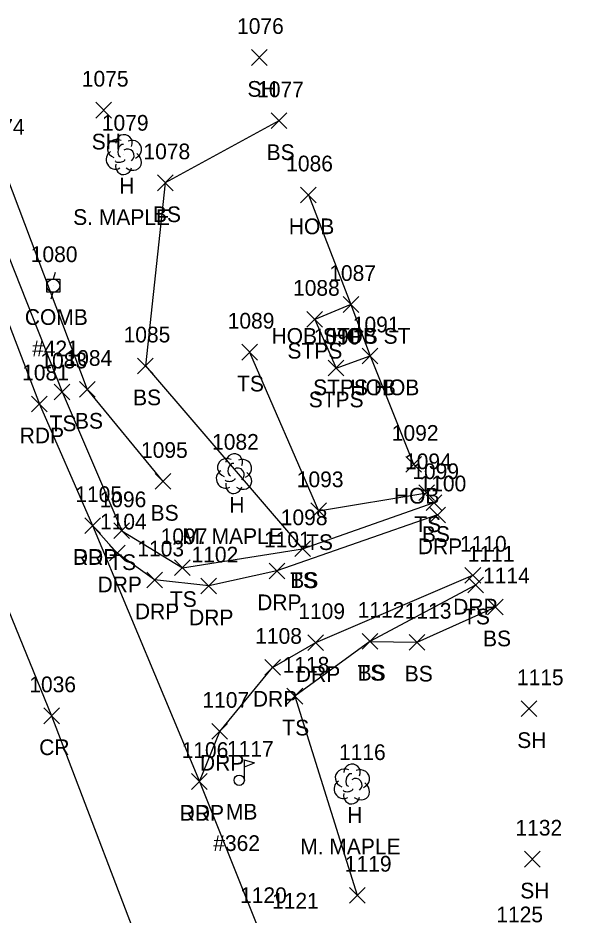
# Model space of a CAD drawing. Extents: x 1651305 to 1654558, y 539481 to 548441.
# Drawn here: x 1654147.7 to 1654218.4, y 545082.1 to 545196.3 of the extents above; entities that cross this region are included whole.
import ezdxf

# ---------------------------------------------------------------- set-up
doc = ezdxf.new("R2010")
doc.units = 0
for name, color, linetype in [('L_A', 7, 'Continuous'), ('L_C', 7, 'Continuous'), ('L_I', 7, 'Continuous'), ('L_TIC', 7, 'Continuous'), ('LBC', 7, 'Continuous'), ('LBF', 7, 'Continuous'), ('LELB', 7, 'Continuous'), ('LMB', 7, 'Continuous'), ('LTD', 7, 'Continuous'), ('P_A', 7, 'Continuous'), ('P_I', 7, 'Continuous'), ('P_TIC', 7, 'Continuous'), ('PET', 7, 'Continuous'), ('PRC', 7, 'Continuous'), ('R_A', 7, 'Continuous'), ('R_I', 7, 'Continuous'), ('R_TIC', 7, 'Continuous'), ('RDP', 7, 'Continuous'), ('U_A', 7, 'Continuous'), ('U_C', 7, 'Continuous'), ('U_I', 7, 'Continuous'), ('UP', 7, 'Continuous')]:
    doc.layers.add(name, color=color, linetype=linetype)

msp = doc.modelspace()

# ---------------------------------------------------------------- linework, layer by layer
at = {"layer": 'L_TIC'}
for points in [[(1654177.39, 545190.31), (1654179.39, 545192.31)], [(1654179.39, 545190.31), (1654177.39, 545192.31)], [(1654157.57, 545183.6), (1654159.57, 545185.6)], [(1654159.57, 545183.6), (1654157.57, 545185.6)], [(1654179.89, 545182.25), (1654181.89, 545184.25)], [(1654181.89, 545182.25), (1654179.89, 545184.25)], [(1654165.41, 545174.35), (1654167.41, 545176.35)], [(1654167.41, 545174.35), (1654165.41, 545176.35)], [(1654183.65, 545172.81), (1654185.65, 545174.81)], [(1654185.65, 545172.81), (1654183.65, 545174.81)], [(1654189.07, 545158.86), (1654191.07, 545160.86)], [(1654191.07, 545158.86), (1654189.07, 545160.86)], [(1654189.07, 545158.86), (1654191.07, 545160.86)], [(1654191.07, 545158.86), (1654189.07, 545160.86)], [(1654184.46, 545156.97), (1654186.46, 545158.97)], [(1654186.46, 545156.97), (1654184.46, 545158.97)], [(1654176.15, 545152.79), (1654178.15, 545154.79)], [(1654178.15, 545152.79), (1654176.15, 545154.79)], [(1654191.5, 545152.31), (1654193.5, 545154.31)], [(1654193.5, 545152.31), (1654191.5, 545154.31)], [(1654191.5, 545152.31), (1654193.5, 545154.31)], [(1654193.5, 545152.31), (1654191.5, 545154.31)], [(1654162.88, 545151.03), (1654164.88, 545153.03)], [(1654164.88, 545151.03), (1654162.88, 545153.03)], [(1654187.17, 545150.77), (1654189.17, 545152.77)], [(1654189.17, 545150.77), (1654187.17, 545152.77)], [(1654155.48, 545148.05), (1654157.48, 545150.05)], [(1654157.48, 545148.05), (1654155.48, 545150.05)], [(1654152.28, 545147.73), (1654154.28, 545149.73)], [(1654154.28, 545147.73), (1654152.28, 545149.73)], [(1654197.04, 545138.51), (1654199.04, 545140.51)], [(1654199.04, 545138.51), (1654197.04, 545140.51)], [(1654165.11, 545136.33), (1654167.11, 545138.33)], [(1654167.11, 545136.33), (1654165.11, 545138.33)], [(1654198.72, 545134.89), (1654200.72, 545136.89)], [(1654200.72, 545134.89), (1654198.72, 545136.89)], [(1654199.66, 545133.63), (1654201.66, 545135.63)], [(1654201.66, 545133.63), (1654199.66, 545135.63)], [(1654184.94, 545132.6), (1654186.94, 545134.6)], [(1654186.94, 545132.6), (1654184.94, 545134.6)], [(1654159.88, 545130.05), (1654161.88, 545132.05)], [(1654161.88, 545130.05), (1654159.88, 545132.05)], [(1654182.9, 545127.76), (1654184.9, 545129.76)], [(1654184.9, 545127.76), (1654182.9, 545129.76)], [(1654182.9, 545127.76), (1654184.9, 545129.76)], [(1654184.9, 545127.76), (1654182.9, 545129.76)], [(1654167.6, 545125.35), (1654169.6, 545127.35)], [(1654169.6, 545125.35), (1654167.6, 545127.35)], [(1654204.94, 545123.13), (1654206.94, 545125.13)], [(1654206.94, 545123.13), (1654204.94, 545125.13)], [(1654207.45, 545120.34), (1654209.45, 545122.34)], [(1654209.45, 545120.34), (1654207.45, 545122.34)], [(1654191.48, 545115.97), (1654193.48, 545117.97)], [(1654193.48, 545115.97), (1654191.48, 545117.97)], [(1654191.48, 545115.97), (1654193.48, 545117.97)], [(1654193.48, 545115.97), (1654191.48, 545117.97)], [(1654197.48, 545115.86), (1654199.48, 545117.86)], [(1654199.48, 545115.86), (1654197.48, 545117.86)], [(1654181.92, 545108.99), (1654183.92, 545110.99)], [(1654183.92, 545108.99), (1654181.92, 545110.99)], [(1654211.75, 545107.39), (1654213.75, 545109.39)], [(1654213.75, 545107.39), (1654211.75, 545109.39)], [(1654212.15, 545088.24), (1654214.15, 545090.24)], [(1654214.15, 545088.24), (1654212.15, 545090.24)], [(1654189.86, 545083.65), (1654191.86, 545085.65)], [(1654191.86, 545083.65), (1654189.86, 545085.65)]]:
    msp.add_lwpolyline(points, dxfattribs=at)
at = {"layer": 'LBC'}
msp.add_lwpolyline([(1654184.65, 545173.81), (1654190.07, 545159.86), (1654192.5, 545153.31), (1654198.04, 545139.51)], dxfattribs=at)
at = {"layer": 'LBF'}
msp.add_lwpolyline([(1654190.07, 545159.86), (1654185.46, 545157.97), (1654188.17, 545151.77), (1654192.5, 545153.31)], dxfattribs=at)
at = {"layer": 'LELB'}
for points in [[(1654180.89, 545183.25), (1654166.41, 545175.35), (1654163.88, 545152.03), (1654183.9, 545128.76), (1654200.66, 545134.63)], [(1654145.32, 545178.48), (1654156.48, 545149.05), (1654166.11, 545137.33)], [(1654141.91, 545177.38), (1654153.28, 545148.73), (1654160.88, 545131.05), (1654168.6, 545126.35), (1654183.9, 545128.76)], [(1654177.15, 545153.79), (1654185.94, 545133.6), (1654199.72, 545135.89)], [(1654205.94, 545124.13), (1654192.48, 545116.97), (1654182.92, 545109.99), (1654190.86, 545084.65)], [(1654192.48, 545116.97), (1654198.48, 545116.86), (1654208.45, 545121.34)]]:
    msp.add_lwpolyline(points, dxfattribs=at)
at = {"layer": 'LMB'}
for p, q in [((1654176.48, 545101.88), (1654177.78, 545101.5)), ((1654176.49, 545099.29), (1654176.49, 545101.89)), ((1654176.49, 545100.98), (1654177.77, 545101.49)), ((1654175.84, 545099.28), (1654175.84, 545099.28))]:
    msp.add_line(p, q, dxfattribs=at)
msp.add_circle((1654175.84, 545099.28), 0.656, dxfattribs=at)
at = {"layer": 'LTD'}
for p, q in [((1654161.12, 545178.99), (1654161.12, 545178.99)), ((1654161.12, 545178.99), (1654161.12, 545178.99)), ((1654175.15, 545138.37), (1654175.15, 545138.37)), ((1654175.15, 545138.37), (1654175.15, 545138.37)), ((1654190.16, 545098.86), (1654190.16, 545098.86)), ((1654190.16, 545098.86), (1654190.16, 545098.86))]:
    msp.add_line(p, q, dxfattribs=at)
for centre in [(1654161.17, 545180.43), (1654175.2, 545139.8), (1654190.2, 545100.29)]:
    msp.add_arc(centre, 1.05, 335.5272, 180.9563, dxfattribs=at)
for centre, major_axis, ratio, start_param, end_param in [((1654160.33, 545179.66), (1.21, -0.51), 0.895232, 1.570796, 4.712389), ((1654162.16, 545179.58), (-1.14, -0.48), 0.949671, 1.570796, 4.712389), ((1654160.91, 545179.45), (-0.208, -0.792), 0.645439, 3.141593, 6.283185), ((1654161.62, 545178.83), (-0.5, 0.667), 0.989748, 3.141593, 6.283185), ((1654160.04, 545178.28), (0.58, -1.04), 0.959034, 3.141593, 6.283185), ((1654162.12, 545178.16), (-1.09, 0.79), 0.841452, 1.570796, 4.712389), ((1654161.12, 545177.49), (0.26, 1.06), 0.942809, 1.570796, 4.712389), ((1654160.66, 545178.24), (-0.625, -0.083), 0.423636, 0, 3.141593), ((1654174.36, 545139.04), (1.21, -0.51), 0.895232, 1.570796, 4.712389), ((1654174.94, 545138.83), (-0.208, -0.792), 0.645439, 3.141593, 6.283185), ((1654176.19, 545138.95), (-1.14, -0.48), 0.949671, 1.570796, 4.712389), ((1654174.07, 545137.66), (0.58, -1.04), 0.959034, 3.141593, 6.283185), ((1654175.65, 545138.2), (-0.5, 0.667), 0.989748, 3.141593, 6.283185), ((1654174.69, 545137.62), (-0.625, -0.083), 0.423636, 0, 3.141593), ((1654176.15, 545137.54), (-1.09, 0.79), 0.841452, 1.570796, 4.712389), ((1654175.15, 545136.87), (0.26, 1.06), 0.942809, 1.570796, 4.712389), ((1654189.36, 545099.52), (1.21, -0.51), 0.895232, 1.570796, 4.712389), ((1654189.95, 545099.31), (-0.208, -0.792), 0.645439, 3.141593, 6.283185), ((1654191.2, 545099.44), (-1.14, -0.48), 0.949671, 1.570796, 4.712389), ((1654189.07, 545098.15), (0.58, -1.04), 0.959034, 3.141593, 6.283185), ((1654190.66, 545098.69), (-0.5, 0.667), 0.989748, 3.141593, 6.283185), ((1654191.16, 545098.02), (-1.09, 0.79), 0.841452, 1.570796, 4.712389), ((1654190.16, 545097.36), (0.26, 1.06), 0.942809, 1.570796, 4.712389), ((1654189.7, 545098.11), (-0.625, -0.083), 0.423636, 0, 3.141593)]:
    msp.add_ellipse(centre, major_axis=major_axis, ratio=ratio, start_param=start_param, end_param=end_param, dxfattribs=at)
at = {"layer": 'P_TIC'}
for points in [[(1654149.39, 545146.19), (1654151.39, 545148.19)], [(1654151.39, 545146.19), (1654149.39, 545148.19)], [(1654156.16, 545130.71), (1654158.16, 545132.71)], [(1654158.16, 545130.71), (1654156.16, 545132.71)], [(1654150.93, 545106.49), (1654152.93, 545108.49)], [(1654152.93, 545106.49), (1654150.93, 545108.49)], [(1654169.76, 545098.13), (1654171.76, 545100.13)], [(1654171.76, 545098.13), (1654169.76, 545100.13)]]:
    msp.add_lwpolyline(points, dxfattribs=at)
at = {"layer": 'PET'}
msp.add_lwpolyline([(1654139.13, 545176.5), (1654150.39, 545147.19), (1654157.16, 545131.71), (1654170.76, 545099.13), (1654178.15, 545080.65), (1654186.44, 545060.96), (1654201.83, 545022.37), (1654207.18, 545004.72), (1654219.14, 544973.24), (1654242.36, 544920.07), (1654247.53, 544907.58), (1654259.28, 544878.11), (1654268.46, 544853.76), (1654271.52, 544840.23), (1654282.76, 544813.43), (1654295.45, 544782.26), (1654306.75, 544753.72), (1654320.35, 544717.46), (1654325.71, 544702.64)], dxfattribs=at)
at = {"layer": 'PRC'}
msp.add_lwpolyline([(1654126.32, 545171.74), (1654141.33, 545133.41), (1654151.93, 545107.49), (1654165.21, 545072.69), (1654175.57, 545046.61), (1654188.97, 545011.94), (1654198.02, 544989.46), (1654207.45, 544965.61), (1654220.75, 544933.07), (1654235.66, 544895.02), (1654251.31, 544856.19), (1654265.06, 544822.16), (1654283.02, 544778.21), (1654298.76, 544737.49), (1654308.6, 544712.81), (1654319.77, 544684.6)], dxfattribs=at)
at = {"layer": 'R_TIC'}
for points in [[(1654200.09, 545132.07), (1654202.09, 545134.07)], [(1654202.09, 545132.07), (1654200.09, 545134.07)], [(1654156.16, 545130.71), (1654158.16, 545132.71)], [(1654158.16, 545130.71), (1654156.16, 545132.71)], [(1654159.31, 545127.22), (1654161.31, 545129.22)], [(1654161.31, 545127.22), (1654159.31, 545129.22)], [(1654179.63, 545124.94), (1654181.63, 545126.94)], [(1654181.63, 545124.94), (1654179.63, 545126.94)], [(1654204.59, 545124.39), (1654206.59, 545126.39)], [(1654206.59, 545124.39), (1654204.59, 545126.39)], [(1654164.06, 545123.79), (1654166.06, 545125.79)], [(1654166.06, 545123.79), (1654164.06, 545125.79)], [(1654170.96, 545123.02), (1654172.96, 545125.02)], [(1654172.96, 545123.02), (1654170.96, 545125.02)], [(1654184.58, 545115.81), (1654186.58, 545117.81)], [(1654186.58, 545115.81), (1654184.58, 545117.81)], [(1654179.08, 545112.66), (1654181.08, 545114.66)], [(1654181.08, 545112.66), (1654179.08, 545114.66)], [(1654172.35, 545104.51), (1654174.35, 545106.51)], [(1654174.35, 545104.51), (1654172.35, 545106.51)], [(1654169.76, 545098.13), (1654171.76, 545100.13)], [(1654171.76, 545098.13), (1654169.76, 545100.13)]]:
    msp.add_lwpolyline(points, dxfattribs=at)
at = {"layer": 'RDP'}
for points in [[(1654201.09, 545133.07), (1654180.63, 545125.94), (1654171.96, 545124.02), (1654165.06, 545124.79), (1654160.31, 545128.22), (1654157.16, 545131.71)], [(1654170.76, 545099.13), (1654173.35, 545105.51), (1654180.08, 545113.66), (1654185.58, 545116.81), (1654205.59, 545125.39)]]:
    msp.add_lwpolyline(points, dxfattribs=at)
at = {"layer": 'UP'}
for p, q in [((1654152.4, 545163.92), (1654152.15, 545163.09)), ((1654151.32, 545161.42), (1654151.32, 545163.09)), ((1654151.32, 545163.09), (1654152.98, 545163.09)), ((1654152.98, 545163.09), (1654152.98, 545161.42)), ((1654152.98, 545161.42), (1654151.32, 545161.42)), ((1654151.9, 545160.59), (1654152.15, 545161.42)), ((1654152.15, 545162.26), (1654152.15, 545162.26))]:
    msp.add_line(p, q, dxfattribs=at)
msp.add_circle((1654152.15, 545162.26), 0.833, dxfattribs=at)

# ---------------------------------------------------------------- texts
at = {"layer": 'L_A'}
for s, p in [('SH', (1654176.88, 545186.31)), ('SH', (1654157.05, 545179.6)), ('BS', (1654179.33, 545178.25)), ('H', (1654160.55, 545173.99)), ('BS', (1654164.85, 545170.35)), ('HOB', (1654182.15, 545168.81)), ('HOB STPS ST', (1654179.95, 545154.86)), ('HOB', (1654187.57, 545154.86)), ('STPS', (1654181.98, 545152.97)), ('TS', (1654175.56, 545148.79)), ('STPS HOB', (1654185.25, 545148.31)), ('HOB', (1654190, 545148.31)), ('BS', (1654162.32, 545147.03)), ('STPS', (1654184.69, 545146.77)), ('TS', (1654151.69, 545143.73)), ('BS', (1654154.92, 545144.05)), ('HOB', (1654195.54, 545134.51)), ('H', (1654174.58, 545133.37)), ('BS', (1654164.55, 545132.33)), ('TS', (1654198.13, 545130.89)), ('BS', (1654199.1, 545129.63)), ('TS', (1654184.35, 545128.6)), ('TS', (1654159.29, 545126.05)), ('TS', (1654182.31, 545123.76)), ('BS', (1654182.34, 545123.76)), ('TS', (1654167.01, 545121.35)), ('TS', (1654204.35, 545119.13)), ('BS', (1654206.89, 545116.34)), ('TS', (1654190.89, 545111.97)), ('BS', (1654190.92, 545111.97)), ('BS', (1654196.92, 545111.86)), ('TS', (1654181.33, 545104.99)), ('SH', (1654211.24, 545103.39)), ('MB', (1654174.14, 545094.28)), ('H', (1654189.59, 545093.86)), ('SH', (1654211.63, 545084.24))]:
    msp.add_text(s, height=2, dxfattribs=at).set_placement(p)
at = {"layer": 'L_C'}
for s, p in [('S. MAPLE', (1654154.69, 545169.99)), ('M. MAPLE', (1654168.6, 545129.37)), ('#362', (1654172.53, 545090.28)), ('M. MAPLE', (1654183.6, 545089.86))]:
    msp.add_text(s, height=2, dxfattribs=at).set_placement(p)
at = {"layer": 'L_I'}
for s, p in [('1076', (1654175.56, 545194.31)), ('1075', (1654155.79, 545187.6)), ('1077', (1654178.12, 545186.25)), ('1074', (1654142.55, 545181.48)), ('1079', (1654158.34, 545181.99)), ('1078', (1654163.64, 545178.35)), ('1086', (1654181.82, 545176.81)), ('1087', (1654187.3, 545162.86)), ('1087', (1654187.3, 545162.86)), ('1088', (1654182.69, 545160.97)), ('1089', (1654174.37, 545156.79)), ('1091', (1654190.3, 545156.31)), ('1091', (1654190.3, 545156.31)), ('1085', (1654161.11, 545155.03)), ('1090', (1654185.32, 545154.77)), ('1083', (1654150.51, 545151.73)), ('1084', (1654153.71, 545152.05)), ('1092', (1654195.27, 545142.51)), ('1082', (1654172.38, 545141.37)), ('1095', (1654163.33, 545140.33)), ('1094', (1654196.95, 545138.89)), ('1099', (1654197.88, 545137.63)), ('1093', (1654183.17, 545136.6)), ('1096', (1654158.05, 545134.05)), ('1098', (1654181.13, 545131.76)), ('1098', (1654181.13, 545131.76)), ('1097', (1654165.83, 545129.35)), ('1111', (1654204.95, 545127.13)), ('1114', (1654206.89, 545124.34)), ('1112', (1654190.92, 545119.97)), ('1112', (1654190.92, 545119.97)), ('1113', (1654196.92, 545119.86)), ('1118', (1654181.36, 545112.99)), ('1115', (1654211.2, 545111.39)), ('1117', (1654174.28, 545102.28)), ('1116', (1654188.54, 545101.86)), ('1132', (1654211.02, 545092.24)), ('1119', (1654189.29, 545087.65))]:
    msp.add_text(s, height=2, dxfattribs=at).set_placement(p)
at = {"layer": 'P_A'}
for s, p in [('RDP', (1654147.88, 545142.19)), ('RDP', (1654154.65, 545126.71)), ('CR', (1654150.36, 545102.49)), ('RDP', (1654168.25, 545094.13))]:
    msp.add_text(s, height=2, dxfattribs=at).set_placement(p)
at = {"layer": 'P_I'}
for s, p in [('1081', (1654148.19, 545150.19)), ('1105', (1654154.96, 545134.71)), ('1036', (1654149.1, 545110.49)), ('1106', (1654168.5, 545102.13)), ('1120', (1654175.94, 545083.65))]:
    msp.add_text(s, height=2, dxfattribs=at).set_placement(p)
at = {"layer": 'R_A'}
for p in [(1654198.58, 545128.07), (1654154.65, 545126.71), (1654157.79, 545123.22), (1654178.12, 545120.94), (1654162.55, 545119.79), (1654203.08, 545120.39), (1654169.45, 545119.02), (1654183.06, 545111.81), (1654177.57, 545108.66), (1654170.84, 545100.51), (1654168.25, 545094.13)]:
    msp.add_text('DRP', height=2, dxfattribs=at).set_placement(p)
at = {"layer": 'R_I'}
for s, p in [('1100', (1654198.8, 545136.07)), ('1105', (1654154.96, 545134.71)), ('1104', (1654158.1, 545131.22)), ('1101', (1654178.99, 545128.94)), ('1103', (1654162.86, 545127.79)), ('1110', (1654203.95, 545128.39)), ('1102', (1654169.76, 545127.02)), ('1109', (1654183.36, 545119.81)), ('1108', (1654177.87, 545116.66)), ('1107', (1654171.15, 545108.51)), ('1106', (1654168.5, 545102.13)), ('1120', (1654175.94, 545083.65)), ('1121', (1654180.02, 545082.94)), ('1125', (1654208.58, 545081.2))]:
    msp.add_text(s, height=2, dxfattribs=at).set_placement(p)
at = {"layer": 'U_A'}
msp.add_text('COMB', height=2, dxfattribs=at).set_placement((1654148.53, 545157.26))
at = {"layer": 'U_C'}
msp.add_text('#421', height=2, dxfattribs=at).set_placement((1654149.46, 545153.26))
at = {"layer": 'U_I'}
msp.add_text('1080', height=2, dxfattribs=at).set_placement((1654149.29, 545165.26))

doc.saveas('drawing.dxf')
